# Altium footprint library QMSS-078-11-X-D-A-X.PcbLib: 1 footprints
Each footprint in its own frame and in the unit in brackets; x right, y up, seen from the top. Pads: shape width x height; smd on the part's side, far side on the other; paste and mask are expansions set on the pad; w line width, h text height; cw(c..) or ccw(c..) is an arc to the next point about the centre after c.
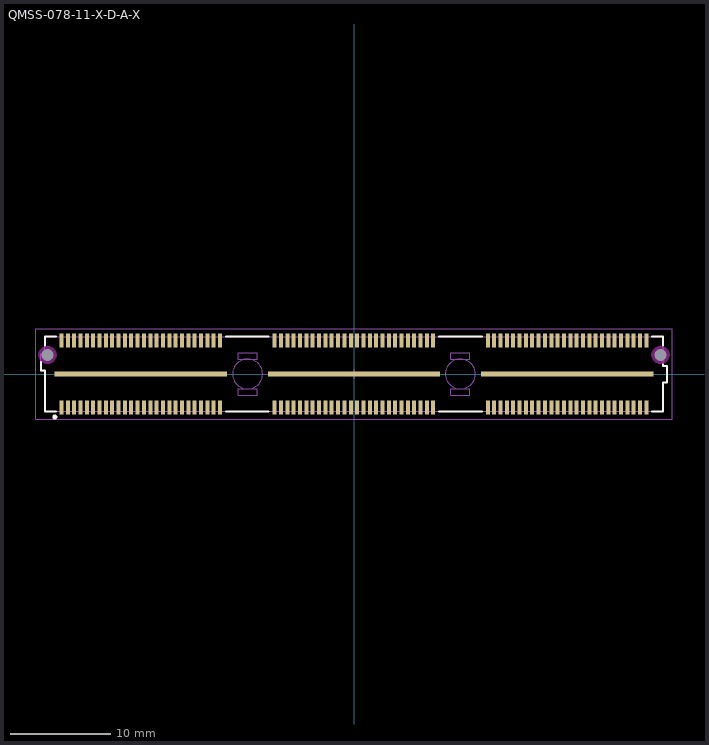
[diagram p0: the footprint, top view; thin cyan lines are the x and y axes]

## QMSS-078-11-X-D-A-X [mm] "0.635mm pitch, 156 pin, shielded header; w/3 banks, w/52 pins/bank, w/40 signals/bank, w/12 GND pin/bank"
height 6.35
pads (161):
  rect 0.4x1.4 smd mask+0: 1(-29.284,-3.365) 2(-29.284,3.365) 3(-28.649,-3.365) 4(-28.649,3.365) 5(-28.014,-3.365) 6(-28.014,3.365) 7(-27.379,-3.365) 8(-27.379,3.365) 9(-26.744,-3.365) 10(-26.744,3.365) 11(-26.109,-3.365) 12(-26.109,3.365) 13(-25.474,-3.365) 14(-25.474,3.365) 15(-24.839,-3.365) 16(-24.839,3.365) 17(-24.204,-3.365) 18(-24.204,3.365) 19(-23.569,-3.365) 20(-23.569,3.365) 21(-22.934,-3.365) 22(-22.934,3.365) 23(-22.299,-3.365) 24(-22.299,3.365) 25(-21.664,-3.365) 26(-21.664,3.365) 27(-21.029,-3.365) 28(-21.029,3.365) 29(-20.394,-3.365) 30(-20.394,3.365) 31(-19.759,-3.365) 32(-19.759,3.365) 33(-19.124,-3.365) 34(-19.124,3.365) 35(-18.489,-3.365) 36(-18.489,3.365) 37(-17.854,-3.365) 38(-17.854,3.365) 39(-17.219,-3.365) 40(-17.219,3.365) 41(-16.584,-3.365) 42(-16.584,3.365) 43(-15.949,-3.365) 44(-15.949,3.365) 45(-15.314,-3.365) 46(-15.314,3.365) 47(-14.679,-3.365) 48(-14.679,3.365) 49(-14.044,-3.365) 50(-14.044,3.365) 51(-13.409,-3.365) 52(-13.409,3.365) 53(-7.944,-3.365) 54(-7.944,3.365) 55(-7.309,-3.365) 56(-7.309,3.365) 57(-6.674,-3.365) 58(-6.674,3.365) 59(-6.039,-3.365) 60(-6.039,3.365) 61(-5.404,-3.365) 62(-5.404,3.365) 63(-4.769,-3.365) 64(-4.769,3.365) 65(-4.134,-3.365) 66(-4.134,3.365) 67(-3.499,-3.365) 68(-3.499,3.365) 69(-2.864,-3.365) 70(-2.864,3.365) 71(-2.229,-3.365) 72(-2.229,3.365) 73(-1.594,-3.365) 74(-1.594,3.365) 75(-0.959,-3.365) 76(-0.959,3.365) 77(-0.324,-3.365) 78(-0.324,3.365) 79(0.311,-3.365) 80(0.311,3.365) 81(0.946,-3.365) 82(0.946,3.365) 83(1.581,-3.365) 84(1.581,3.365) 85(2.216,-3.365) 86(2.216,3.365) 87(2.851,-3.365) 88(2.851,3.365) 89(3.486,-3.365) 90(3.486,3.365) 91(4.121,-3.365) 92(4.121,3.365) 93(4.756,-3.365) 94(4.756,3.365) 95(5.391,-3.365) 96(5.391,3.365) 97(6.026,-3.365) 98(6.026,3.365) 99(6.661,-3.365) 100(6.661,3.365) 101(7.296,-3.365) 102(7.296,3.365) 103(7.931,-3.365) 104(7.931,3.365) 105(13.396,-3.365) 106(13.396,3.365) 107(14.031,-3.365) 108(14.031,3.365) 109(14.666,-3.365) 110(14.666,3.365) 111(15.301,-3.365) 112(15.301,3.365) 113(15.936,-3.365) 114(15.936,3.365) 115(16.571,-3.365) 116(16.571,3.365) 117(17.206,-3.365) 118(17.206,3.365) 119(17.841,-3.365) 120(17.841,3.365) 121(18.476,-3.365) 122(18.476,3.365) 123(19.111,-3.365) 124(19.111,3.365) 125(19.746,-3.365) 126(19.746,3.365) 127(20.381,-3.365) 128(20.381,3.365) 129(21.016,-3.365) 130(21.016,3.365) 131(21.651,-3.365) 132(21.651,3.365) 133(22.286,-3.365) 134(22.286,3.365) 135(22.921,-3.365) 136(22.921,3.365) 137(23.556,-3.365) 138(23.556,3.365) 139(24.191,-3.365) 140(24.191,3.365) 141(24.826,-3.365) 142(24.826,3.365) 143(25.461,-3.365) 144(25.461,3.365) 145(26.096,-3.365) 146(26.096,3.365) 147(26.731,-3.365) 148(26.731,3.365) 149(27.366,-3.365) 150(27.366,3.365) 151(28.001,-3.365) 152(28.001,3.365) 153(28.636,-3.365) 154(28.636,3.365) 155(29.271,-3.365) 156(29.271,3.365)
  rect 17.25x0.5 smd mask+0: 157(-21.344,0) 158(-0.004,0) 159(21.336,0)
  round 1 hole 1.2 unplated mask+0: 160(-30.679,1.91) 161(30.679,1.91)
Top Overlay:
  circle w0.25: c-29.95,-4.3 r0.125
  lines w0.2: -31.35,1.2 -31.35,0.35 -30.95,0.35 -30.95,-3.75 -29.85,-3.75 ; -30.95,2.85 -30.95,3.75 -29.85,3.75 ; -12.8,-3.75 -8.55,-3.75 ; -12.8,3.75 -8.55,3.75 ; 8.5,-3.75 12.8,-3.75 ; 8.5,3.75 12.8,3.75 ; 29.85,-3.75 30.95,-3.75 30.95,-0.85 31.35,-0.85 31.35,0.8 30.95,0.8 30.95,0.95 ; 29.85,3.75 30.95,3.75 30.95,2.85
Keep-Out Layer:
  pour cut-out: 31.587,1.91 31.556,2.145 31.465,2.364 31.321,2.552 31.133,2.696 30.914,2.787 30.679,2.818 30.444,2.787 30.225,2.696 30.037,2.552 29.893,2.364 29.802,2.145 29.771,1.91 29.802,1.675 29.893,1.456 30.037,1.268 30.225,1.124 30.444,1.033 30.679,1.002 30.914,1.033 31.133,1.124 31.321,1.268 31.465,1.456 31.556,1.675
  pour cut-out: -29.771,1.91 -29.802,2.145 -29.893,2.364 -30.037,2.552 -30.225,2.696 -30.444,2.787 -30.679,2.818 -30.914,2.787 -31.133,2.696 -31.321,2.552 -31.465,2.364 -31.556,2.145 -31.587,1.91 -31.556,1.675 -31.465,1.456 -31.321,1.268 -31.133,1.124 -30.914,1.033 -30.679,1.002 -30.444,1.033 -30.225,1.124 -30.037,1.268 -29.893,1.456 -29.802,1.675
Mechanical 12:
  lines w0.001: -31.35,0.35 -31.35,2.02 -30.95,2.02 -30.95,3.75 30.95,3.75 30.95,0.8 31.35,0.8 31.35,-0.85 30.95,-0.85 30.95,-3.75 -30.95,-3.75 -30.95,0.35 -31.35,0.35
Mechanical 13:
  circle w0.1: c-10.65,0 r1.5
  circle w0.1: c10.65,0 r1.5
  lines w0.1: -31.35,0.35 -31.35,2.02 -30.95,2.02 -30.95,3.75 30.95,3.75 30.95,0.8 31.35,0.8 31.35,-0.85 30.95,-0.85 30.95,-3.75 -30.95,-3.75 -30.95,0.35 -31.35,0.35 ; -11.6,-2.15 -11.6,-1.5 -9.7,-1.5 -9.7,-2.15 -11.6,-2.15 ; -11.6,1.5 -11.6,2.15 -9.7,2.15 -9.7,1.5 -11.6,1.5 ; 9.7,-2.15 9.7,-1.5 11.6,-1.5 11.6,-2.15 9.7,-2.15 ; 9.7,1.5 9.7,2.15 11.6,2.15 11.6,1.5 9.7,1.5
  text ".Designator" at 0.25,0.254 h1.52
Mechanical 15:
  lines w0.05: -0.5,0 0.5,0 ; 0,-0.5 0,0.5 ; -31.85,-4.55 -31.85,4.55 31.85,4.55 31.85,-4.55 -31.85,-4.55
